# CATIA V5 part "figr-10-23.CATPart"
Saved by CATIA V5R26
Part number: Part1
Bounding box of the stored display mesh (mm): x -174.518 to 0, y -36.805 to 36.805, z 0 to 36.805
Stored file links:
  D:\_Deepak\CATIA\CATIA V5-6R2016_Deepak\Resources\Part files\Partfiles\c10_catia_v5_6r2016_prt\figr-10-23.CATPart
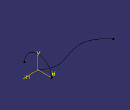
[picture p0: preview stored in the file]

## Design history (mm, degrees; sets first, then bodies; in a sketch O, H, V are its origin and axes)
Body1 (main body)
  Sketch1 on xy-plane, origin (0, 0, 0), H (1, 0, 0), V (0, 1, 0)
    spline S1 through (0, 0) (-31.5913, 14.7273) (-94.8038, 0) (-174.5181, 29.5113)
    point P1 (0, 0)
    point P2 (-94.8038, 0)
    coincidence: P1 O, P2 H
  Sketch2 on yz-plane, origin (0, 0, 0), H (0, 1, 0), V (0, 0, 1)
    arc A1 centre (0, 0) radius 36.8048 from (36.8048, 0) to (-36.8048, 0) ccw
    point P1 (-36.8048, 0)
    point P2 (36.8048, 0)
    coincidence: P1 H, P2 H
